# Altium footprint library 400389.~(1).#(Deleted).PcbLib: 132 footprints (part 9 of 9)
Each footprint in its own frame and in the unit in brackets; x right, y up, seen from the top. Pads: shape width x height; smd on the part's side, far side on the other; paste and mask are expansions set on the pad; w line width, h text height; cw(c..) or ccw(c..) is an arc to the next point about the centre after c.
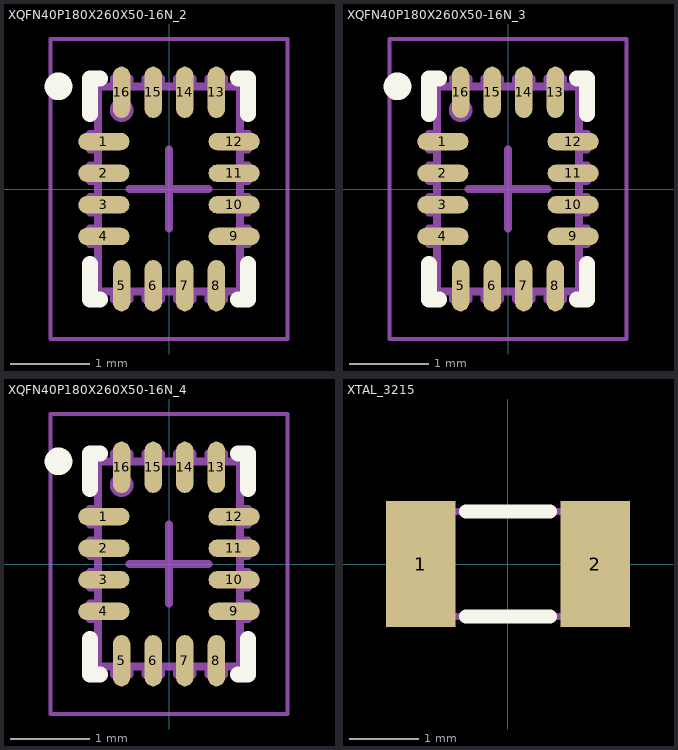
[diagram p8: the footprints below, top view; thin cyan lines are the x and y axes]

## XQFN40P180X260X50-16N_2 [mm]
pads (16):
  oval 0.65x0.22 smd paste-0.02 mask+0.04: 1(-0.825,0.6) 2(-0.825,0.2) 3(-0.825,-0.2) 4(-0.825,-0.6) 9(0.825,-0.6) 10(0.825,-0.2) 11(0.825,0.2) 12(0.825,0.6)
  oval 0.22x0.65 smd paste-0.02 mask+0.04: 5(-0.6,-1.225) 6(-0.2,-1.225) 7(0.2,-1.225) 8(0.6,-1.225) 13(0.6,1.225) 14(0.2,1.225) 15(-0.2,1.225) 16(-0.6,1.225)
Top Overlay:
  circle w0.25: c-1.4,1.3 r0.05
  lines w0.2: -1,-0.95 -1,-1.4 -0.875,-1.4 ; -1,0.95 -1,1.4 -0.875,1.4 ; 0.875,-1.4 1,-1.4 1,-0.95 ; 0.875,1.4 1,1.4 1,0.95
Mechanical 7:
  circle w0.1: c-0.6,1 r0.1
  lines w0.1: -0.9,-0.7 -1,-0.7 -1,-0.5 -0.9,-0.5 ; -0.9,-0.3 -1,-0.3 -1,-0.1 -0.9,-0.1 ; -0.9,0.1 -1,0.1 -1,0.3 -0.9,0.3 ; -0.9,0.5 -1,0.5 -1,0.7 -0.9,0.7 ; -0.7,-1.3 -0.7,-1.4 -0.5,-1.4 -0.5,-1.3 ; -0.7,1.3 -0.7,1.4 -0.5,1.4 -0.5,1.3 ; -0.3,-1.3 -0.3,-1.4 -0.1,-1.4 -0.1,-1.3 ; -0.3,1.3 -0.3,1.4 -0.1,1.4 -0.1,1.3 ; 0.1,-1.3 0.1,-1.4 0.3,-1.4 0.3,-1.3 ; 0.1,1.3 0.1,1.4 0.3,1.4 0.3,1.3 ; 0.5,-1.3 0.5,-1.4 0.7,-1.4 0.7,-1.3 ; 0.5,1.3 0.5,1.4 0.7,1.4 0.7,1.3 ; 0.9,-0.7 1,-0.7 1,-0.5 0.9,-0.5 ; 0.9,-0.3 1,-0.3 1,-0.1 0.9,-0.1 ; 0.9,0.1 1,0.1 1,0.3 0.9,0.3 ; 0.9,0.5 1,0.5 1,0.7 0.9,0.7 ; -0.9,-1.3 0.9,-1.3 0.9,1.3 -0.9,1.3 -0.9,-1.3
  text ".Designator" at -0.45,-0.2 h0.38
Mechanical 15:
  lines w0.05: -1.5,-1.9 1.5,-1.9 1.5,1.9 -1.5,1.9 -1.5,-1.9
  lines w0.1: -0.5,0 0.5,0 ; 0,-0.5 0,0.5
3D body: height 0.55, standoff 0.4, extent -0.9,-0.35 0.9,0.35
3D body "User Library-XQFN-16-1.step": height 0.55, standoff 0, extent -0.91,-1.31 0.91,1.31

## XQFN40P180X260X50-16N_3 [mm]
pads (16):
  oval 0.65x0.22 smd paste-0.02 mask+0.04: 1(-0.825,0.6) 2(-0.825,0.2) 3(-0.825,-0.2) 4(-0.825,-0.6) 9(0.825,-0.6) 10(0.825,-0.2) 11(0.825,0.2) 12(0.825,0.6)
  oval 0.22x0.65 smd paste-0.02 mask+0.04: 5(-0.6,-1.225) 6(-0.2,-1.225) 7(0.2,-1.225) 8(0.6,-1.225) 13(0.6,1.225) 14(0.2,1.225) 15(-0.2,1.225) 16(-0.6,1.225)
Top Overlay:
  circle w0.25: c-1.4,1.3 r0.05
  lines w0.2: -1,-0.95 -1,-1.4 -0.875,-1.4 ; -1,0.95 -1,1.4 -0.875,1.4 ; 0.875,-1.4 1,-1.4 1,-0.95 ; 0.875,1.4 1,1.4 1,0.95
Mechanical 7:
  circle w0.1: c-0.6,1 r0.1
  lines w0.1: -0.9,-0.7 -1,-0.7 -1,-0.5 -0.9,-0.5 ; -0.9,-0.3 -1,-0.3 -1,-0.1 -0.9,-0.1 ; -0.9,0.1 -1,0.1 -1,0.3 -0.9,0.3 ; -0.9,0.5 -1,0.5 -1,0.7 -0.9,0.7 ; -0.7,-1.3 -0.7,-1.4 -0.5,-1.4 -0.5,-1.3 ; -0.7,1.3 -0.7,1.4 -0.5,1.4 -0.5,1.3 ; -0.3,-1.3 -0.3,-1.4 -0.1,-1.4 -0.1,-1.3 ; -0.3,1.3 -0.3,1.4 -0.1,1.4 -0.1,1.3 ; 0.1,-1.3 0.1,-1.4 0.3,-1.4 0.3,-1.3 ; 0.1,1.3 0.1,1.4 0.3,1.4 0.3,1.3 ; 0.5,-1.3 0.5,-1.4 0.7,-1.4 0.7,-1.3 ; 0.5,1.3 0.5,1.4 0.7,1.4 0.7,1.3 ; 0.9,-0.7 1,-0.7 1,-0.5 0.9,-0.5 ; 0.9,-0.3 1,-0.3 1,-0.1 0.9,-0.1 ; 0.9,0.1 1,0.1 1,0.3 0.9,0.3 ; 0.9,0.5 1,0.5 1,0.7 0.9,0.7 ; -0.9,-1.3 0.9,-1.3 0.9,1.3 -0.9,1.3 -0.9,-1.3
  text ".Designator" at -0.45,-0.2 h0.38
Mechanical 15:
  lines w0.05: -1.5,-1.9 1.5,-1.9 1.5,1.9 -1.5,1.9 -1.5,-1.9
  lines w0.1: -0.5,0 0.5,0 ; 0,-0.5 0,0.5
3D body: height 0.55, standoff 0.4, extent -0.9,-0.35 0.9,0.35
3D body "User Library-XQFN-16-1.step": height 0.55, standoff 0, extent -0.91,-1.31 0.91,1.31

## XQFN40P180X260X50-16N_4 [mm]
pads (16):
  oval 0.65x0.22 smd paste-0.02 mask+0.04: 1(-0.825,0.6) 2(-0.825,0.2) 3(-0.825,-0.2) 4(-0.825,-0.6) 9(0.825,-0.6) 10(0.825,-0.2) 11(0.825,0.2) 12(0.825,0.6)
  oval 0.22x0.65 smd paste-0.02 mask+0.04: 5(-0.6,-1.225) 6(-0.2,-1.225) 7(0.2,-1.225) 8(0.6,-1.225) 13(0.6,1.225) 14(0.2,1.225) 15(-0.2,1.225) 16(-0.6,1.225)
Top Overlay:
  circle w0.25: c-1.4,1.3 r0.05
  lines w0.2: -1,-0.95 -1,-1.4 -0.875,-1.4 ; -1,0.95 -1,1.4 -0.875,1.4 ; 0.875,-1.4 1,-1.4 1,-0.95 ; 0.875,1.4 1,1.4 1,0.95
Mechanical 7:
  circle w0.1: c-0.6,1 r0.1
  lines w0.1: -0.9,-0.7 -1,-0.7 -1,-0.5 -0.9,-0.5 ; -0.9,-0.3 -1,-0.3 -1,-0.1 -0.9,-0.1 ; -0.9,0.1 -1,0.1 -1,0.3 -0.9,0.3 ; -0.9,0.5 -1,0.5 -1,0.7 -0.9,0.7 ; -0.7,-1.3 -0.7,-1.4 -0.5,-1.4 -0.5,-1.3 ; -0.7,1.3 -0.7,1.4 -0.5,1.4 -0.5,1.3 ; -0.3,-1.3 -0.3,-1.4 -0.1,-1.4 -0.1,-1.3 ; -0.3,1.3 -0.3,1.4 -0.1,1.4 -0.1,1.3 ; 0.1,-1.3 0.1,-1.4 0.3,-1.4 0.3,-1.3 ; 0.1,1.3 0.1,1.4 0.3,1.4 0.3,1.3 ; 0.5,-1.3 0.5,-1.4 0.7,-1.4 0.7,-1.3 ; 0.5,1.3 0.5,1.4 0.7,1.4 0.7,1.3 ; 0.9,-0.7 1,-0.7 1,-0.5 0.9,-0.5 ; 0.9,-0.3 1,-0.3 1,-0.1 0.9,-0.1 ; 0.9,0.1 1,0.1 1,0.3 0.9,0.3 ; 0.9,0.5 1,0.5 1,0.7 0.9,0.7 ; -0.9,-1.3 0.9,-1.3 0.9,1.3 -0.9,1.3 -0.9,-1.3
  text ".Designator" at -0.45,-0.2 h0.38
Mechanical 15:
  lines w0.05: -1.5,-1.9 1.5,-1.9 1.5,1.9 -1.5,1.9 -1.5,-1.9
  lines w0.1: -0.5,0 0.5,0 ; 0,-0.5 0,0.5
3D body: height 0.55, standoff 0.4, extent -0.9,-0.35 0.9,0.35
3D body "User Library-XQFN-16-1.step": height 0.55, standoff 0, extent -0.91,-1.31 0.91,1.31

## XTAL_3215 [mm]
pads (2):
  rect 1x1.8 smd: 1(-1.25,0) 2(1.25,0)
Top Overlay:
  lines w0.2: -0.6,-0.75 0.6,-0.75 ; -0.6,0.75 0.6,0.75
Mechanical 7:
  lines w0.1: -1.6,-0.75 1.6,-0.75 1.6,0.75 -1.6,0.75 -1.6,-0.75
  text ".Designator" at -0.845,-0.133 h0.38
Mechanical 15:
  lines w0.1: -1.6,-0.55 cw(c-1.6,-0.75) -1.4,-0.75 1.4,-0.75 cw(c1.6,-0.75) 1.6,-0.55 1.6,0.55 cw(c1.6,0.75) 1.4,0.75 -1.4,0.75 cw(c-1.6,0.75) -1.6,0.55 -1.6,-0.55
3D body "User Library-Siward_SX3215.step": height 0.81, standoff 0, extent -1.6,-0.75 1.6,0.75
3D body: height 0.81, standoff 0.15, extent -1.2,-0.6 1.2,0.6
